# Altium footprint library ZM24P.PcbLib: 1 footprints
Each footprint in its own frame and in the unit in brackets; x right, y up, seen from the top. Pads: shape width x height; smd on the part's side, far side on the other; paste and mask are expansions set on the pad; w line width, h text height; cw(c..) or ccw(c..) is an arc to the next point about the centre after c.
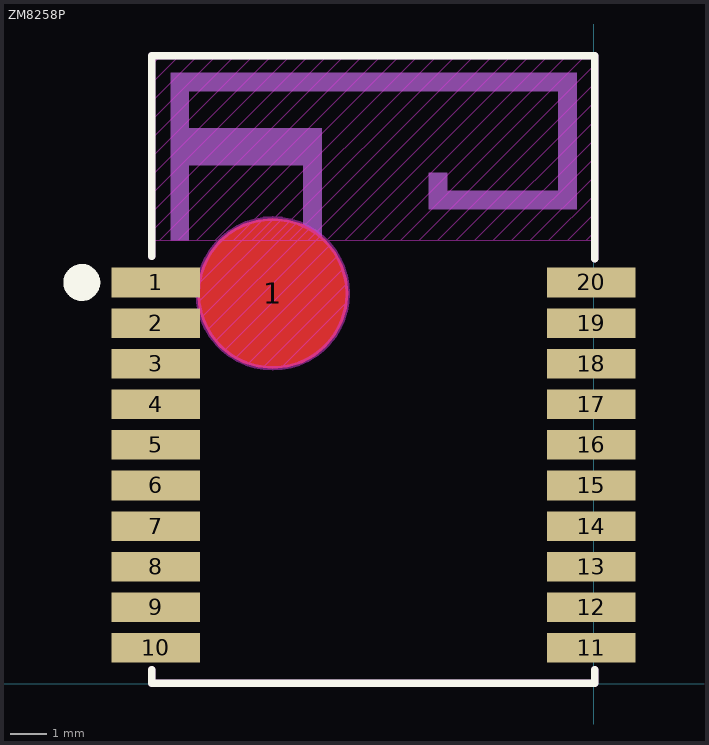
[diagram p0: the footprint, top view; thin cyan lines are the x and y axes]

## ZM8258P [mm] "ZM8258P Rev.A"
height 2.6
pads (21):
  rect 2.4x0.8 smd mask+0.051: 1(-11.876,10.865) 2(-11.876,9.765) 3(-11.876,8.665) 4(-11.876,7.565) 5(-11.876,6.465) 6(-11.876,5.365) 7(-11.876,4.265) 8(-11.876,3.165) 9(-11.876,2.065) 10(-11.876,0.965) 11(-0.076,0.965) 12(-0.076,2.065) 13(-0.076,3.165) 14(-0.076,4.265) 15(-0.076,5.365) 16(-0.076,6.465) 17(-0.076,7.565) 18(-0.076,8.665) 19(-0.076,9.765) 20(-0.076,10.865)
  round 1.016 on Mech15 paste-0.508 mask+0.381: 1(-8.703,10.568)
Top Layer:
  pour cut-out: -10.743,10.568 -10.704,10.17 -10.588,9.787 -10.399,9.435 -10.145,9.126 -9.836,8.872 -9.484,8.683 -9.101,8.567 -8.703,8.528 -8.305,8.567 -7.923,8.683 -7.57,8.872 -7.261,9.126 -7.007,9.435 -6.819,9.787 -6.702,10.17 -6.663,10.568 -6.702,10.966 -6.819,11.349 -7.007,11.701 -7.261,12.01 -7.57,12.264 -7.923,12.453 -8.305,12.569 -8.703,12.608 -9.101,12.569 -9.484,12.453 -9.836,12.264 -10.145,12.01 -10.399,11.701 -10.588,11.349 -10.704,10.966
Top Layer keep-out:
  circle w0.127: c-8.703,10.568 r2.03
  lines w0.025: -10.704,10.339 -8.457,12.585 ; -10.697,10.847 -8.964,12.581 ; -10.61,9.931 -8.039,12.502 ; -10.459,9.58 -7.691,12.347 ; -10.271,9.265 -7.4,12.136 ; -10.02,9.014 -7.149,11.885 ; -9.718,8.814 -6.946,11.586 ; -9.377,8.653 -6.791,11.239 ; -8.967,8.561 -6.682,10.845 ; -8.495,8.53 -6.665,10.36
Top Overlay:
  circle w0.5: c-13.876,10.865 r0.25
  lines w0.2: -11.976,0.375 -11.976,0.005 0.024,0.005 0.024,0.375 ; -11.976,11.576 -11.976,17.005 0.024,17.005 0.024,11.5
Keep-Out Layer:
  lines w0.025: -11.975,12.249 -7.22,17.005 ; -11.975,12.752 -7.722,17.005 ; -11.975,13.254 -8.224,17.005 ; -11.975,13.757 -8.726,17.005 ; -11.975,14.259 -9.228,17.005 ; -11.975,14.761 -9.73,17.005 ; -11.975,15.263 -10.232,17.005 ; -11.975,15.765 -10.734,17.005 ; -11.975,16.267 -11.237,17.005 ; -11.975,16.769 -11.739,17.005 ; -11.763,12.005 -6.763,17.005 ; -11.261,12.005 -6.261,17.005 ; -10.759,12.005 -5.759,17.005 ; -10.256,12.005 -5.256,17.005 ; -9.754,12.005 -4.754,17.005 ; -9.252,12.005 -4.252,17.005 ; -8.75,12.005 -3.75,17.005 ; -8.248,12.005 -3.248,17.005 ; -7.746,12.005 -2.746,17.005 ; -7.244,12.005 -2.244,17.005 ; -6.741,12.005 -1.742,17.005 ; -6.239,12.005 -1.239,17.005 ; -5.737,12.005 -0.736,17.007 ; -5.235,12.005 -0.236,17.005 ; -4.733,12.005 0.023,16.761 ; -4.231,12.005 0.022,16.258 ; -3.729,12.005 0.022,15.756 ; -3.226,12.005 0.022,15.254 ; -2.724,12.005 0.022,14.752 ; -2.222,12.005 0.022,14.25 ; -1.72,12.005 0.022,13.747 ; -1.218,12.005 0.022,13.245 ; -0.716,12.005 0.022,12.743 ; -0.214,12.005 0.022,12.241 ; -11.976,12.005 0.024,12.005 0.024,17.005 -11.976,17.005 -11.976,12.005
Mechanical 15:
  region: -11.473,12.005 -10.973,12.005 -10.973,14.046 -7.873,14.046 -7.873,12.005 -7.373,12.005 -7.373,15.046 -10.973,15.046 -10.973,16.046 -0.973,16.046 -0.973,13.346 -3.973,13.346 -3.973,13.845 -4.473,13.845 -4.473,12.846 -0.473,12.846 -0.473,16.546 -11.473,16.546
  lines w0.2: -11.976,0.375 -11.976,0.005 0.024,0.005 0.024,0.375 ; -11.976,11.576 -11.976,17.005 0.024,17.005 0.024,11.5
  text "各层禁止走线" at -8.986,12.27 h0.76
  text "天线区域" at -8.206,13.177 h0.76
